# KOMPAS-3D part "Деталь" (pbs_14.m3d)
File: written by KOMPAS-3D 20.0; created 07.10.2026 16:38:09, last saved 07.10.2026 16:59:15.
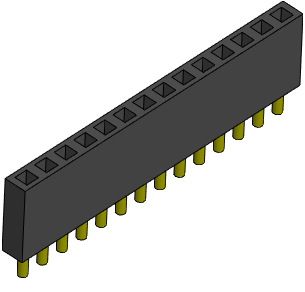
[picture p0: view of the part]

Document properties: Полное имя файла: D:\myProjects\Progect_esp32\box_compas\pbs_14.m3d

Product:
- Part/product: Деталь
    Масса: 0.00428927

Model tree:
1. Эскиз:1
2. Элемент выдавливания:1
     Расстояние 1 = 8.5
3. Эскиз:2  (with: Элемент выдавливания:1)
4. Элемент выдавливания:2
     Расстояние 1 = 3
5. Массив по сетке:2  (with: Элемент выдавливания:2, Эскиз:2)  (14 pattern instances)
     Шаг 1 = 2.54; Угол раствора = 90
6. Эскиз:3  (with: Элемент выдавливания:1)
7. Элемент выдавливания:3
     Расстояние 2 = 8
8. Массив по сетке:3  (with: Элемент выдавливания:3, Эскиз:3)  (14 pattern instances)
     Шаг 1 = 2.54; Угол раствора = 90; Геометрический массив = 128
